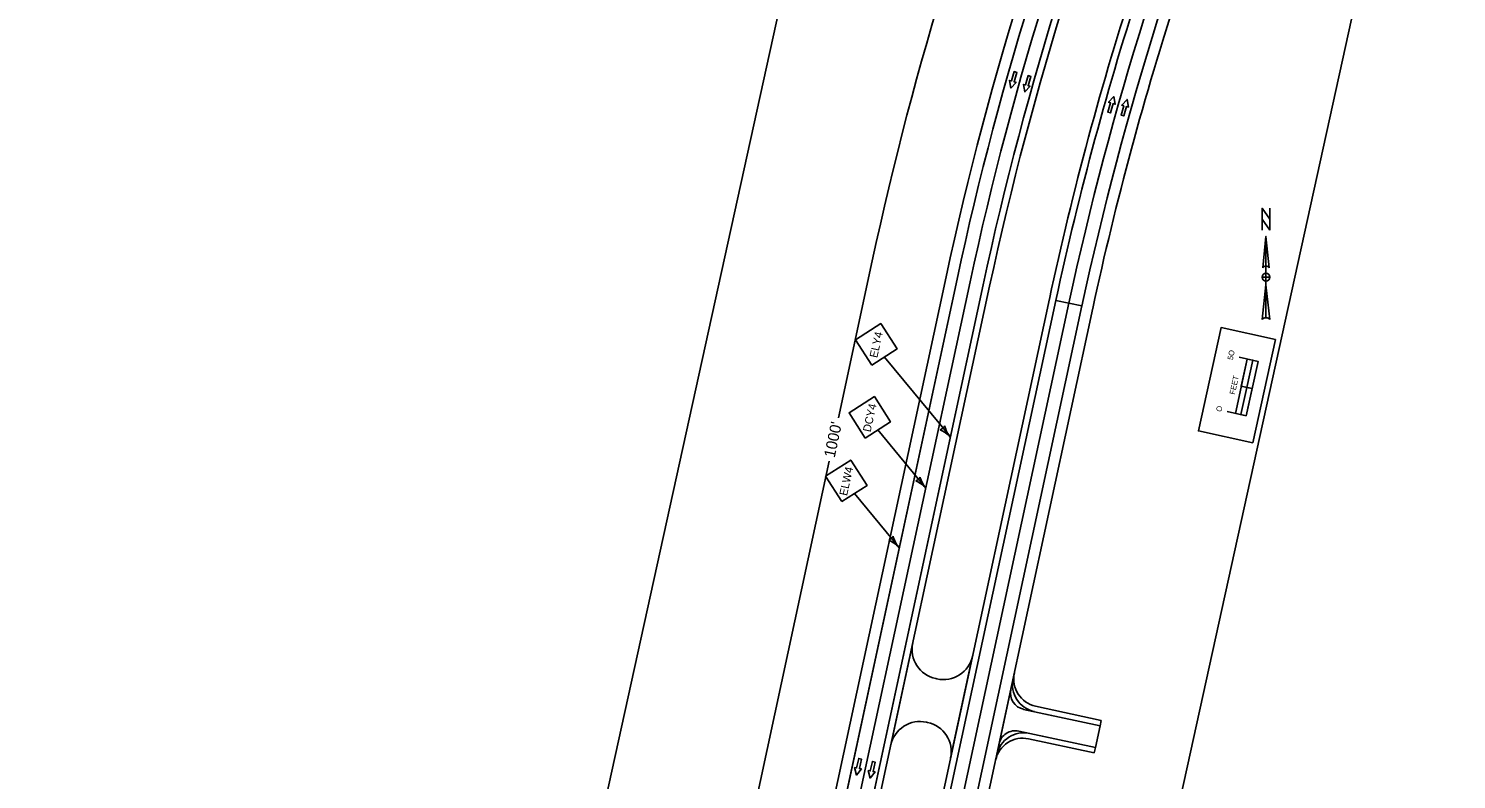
# Model space of a CAD drawing. Extents: x 14104283 to 14121738, y 8635219 to 8671666.
# Drawn here: x 14108141 to 14109426, y 8644454 to 8645129 of the extents above; entities that cross this region are included whole.
import ezdxf

# ---------------------------------------------------------------- set-up
doc = ezdxf.new("R2010")
doc.units = 0
for name, color, linetype in [('Cell', 7, 'Continuous'), ('Default', 7, 'Continuous'), ('dsnCellsNorthArrow', 7, 'Continuous'), ('dsnCellsScaleBlock', 7, 'Continuous'), ('dsnNonPlotable', 7, 'Continuous'), ('dsnPaintExistingBrokenLaneLineWhite', 7, 'Continuous'), ('dsnPaintExistingEdgeLineLeftYellow', 7, 'Continuous'), ('dsnPaintExistingEdgeLineRightWhite', 7, 'Continuous'), ('dsnShadingPaved', 7, 'Continuous'), ('dsnStdLabel', 7, 'Continuous'), ('dsnStgShadingPrevPav', 7, 'Continuous')]:
    doc.layers.add(name, color=color, linetype=linetype)

msp = doc.modelspace()

# ---------------------------------------------------------------- linework, layer by layer
at = {"layer": 'Cell'}
for points in [[(14109027.8, 8645090.4), (14109030.2, 8645089.7), (14109027.7, 8645081.3), (14109029.5, 8645080.7), (14109024.8, 8645075.6), (14109023.5, 8645082.5), (14109025.3, 8645082)], [(14109040.4, 8645086.8), (14109042.8, 8645086.1), (14109040.3, 8645077.7), (14109042.1, 8645077.2), (14109037.4, 8645072.1), (14109036.1, 8645078.9), (14109037.9, 8645078.4)], [(14109114.4, 8645053.2), (14109112, 8645054), (14109114.5, 8645062.3), (14109112.7, 8645062.9), (14109117.4, 8645068), (14109118.7, 8645061.1), (14109116.9, 8645061.6)], [(14109126.3, 8645050.6), (14109123.9, 8645051.3), (14109126.3, 8645059.7), (14109124.5, 8645060.3), (14109129.3, 8645065.4), (14109130.5, 8645058.5), (14109128.7, 8645059)], [(14108887.8, 8644472.9), (14108890.2, 8644472.3), (14108888.4, 8644463.8), (14108890.2, 8644463.4), (14108885.8, 8644457.9), (14108884.1, 8644464.7), (14108885.9, 8644464.3)], [(14108900.1, 8644470.2), (14108902.5, 8644469.6), (14108900.7, 8644461.1), (14108902.5, 8644460.7), (14108898.1, 8644455.2), (14108896.4, 8644462), (14108898.2, 8644461.6)]]:
    msp.add_lwpolyline(points, close=True, dxfattribs=at)
for points in [[(14109025.3, 8645082), (14109023.5, 8645082.5), (14109024.8, 8645075.6), (14109029.5, 8645080.7), (14109027.7, 8645081.3), (14109030.2, 8645089.7), (14109027.8, 8645090.4), (14109025.3, 8645082)], [(14109037.9, 8645078.4), (14109036.1, 8645078.9), (14109037.4, 8645072.1), (14109042.1, 8645077.2), (14109040.3, 8645077.7), (14109042.8, 8645086.1), (14109040.4, 8645086.8), (14109037.9, 8645078.4)], [(14109116.9, 8645061.6), (14109118.7, 8645061.1), (14109117.4, 8645068), (14109112.7, 8645062.9), (14109114.5, 8645062.3), (14109112, 8645054), (14109114.4, 8645053.2), (14109116.9, 8645061.6)], [(14109128.7, 8645059), (14109130.5, 8645058.5), (14109129.3, 8645065.4), (14109124.5, 8645060.3), (14109126.3, 8645059.7), (14109123.9, 8645051.3), (14109126.3, 8645050.6), (14109128.7, 8645059)], [(14108885.9, 8644464.3), (14108884.1, 8644464.7), (14108885.8, 8644457.9), (14108890.2, 8644463.4), (14108888.4, 8644463.8), (14108890.2, 8644472.3), (14108887.8, 8644472.9), (14108885.9, 8644464.3)], [(14108898.2, 8644461.6), (14108896.4, 8644462), (14108898.1, 8644455.2), (14108902.5, 8644460.7), (14108900.7, 8644461.1), (14108902.5, 8644469.6), (14108900.1, 8644470.2), (14108898.2, 8644461.6)]]:
    msp.add_lwpolyline(points, dxfattribs=at)
at = {"layer": 'Default'}
for p, q in [((14108700.5, 8643190.8), (14109065.3, 8644884.7)), ((14109088.7, 8644879.7), (14108724, 8643185.8)), ((14109065.3, 8644884.7), (14109088.7, 8644879.7))]:
    msp.add_line(p, q, dxfattribs=at)
for points in [[(14108976.3, 8644903.9), (14108611.6, 8643210.2), (14108202.1, 8641346.1)], [(14108434.9, 8642294.1), (14108635.1, 8643205.1), (14108999.8, 8644898.8)]]:
    msp.add_lwpolyline(points, dxfattribs=at)
for radius in [2968, 2944]:
    msp.add_arc((14111877.8, 8644279.1), radius, 157.1547, 167.8488, dxfattribs=at)
at = {"layer": 'dsnCellsNorthArrow'}
for p, q in [((14109254.3, 8644942.2), (14109257.1, 8644914.1)), ((14109254.3, 8644942.2), (14109254.3, 8644869)), ((14109251.5, 8644914.1), (14109251.5, 8644914.1)), ((14109251.6, 8644914.3), (14109252.1, 8644914.9)), ((14109250.8, 8644867.6), (14109254.3, 8644898.6)), ((14109254.3, 8644902.1), (14109254.3, 8644902.1))]:
    msp.add_line(p, q, dxfattribs=at)
msp.add_lwpolyline([(14109257.8, 8644947.9), (14109250.8, 8644957.7), (14109250.8, 8644967.6), (14109257.8, 8644957.7)], close=True, dxfattribs=at)
for points in [[(14109250.8, 8644947.9), (14109250.8, 8644967.6), (14109257.8, 8644957.7), (14109257.8, 8644967.6)], [(14109251.5, 8644914.1), (14109254.3, 8644942.2), (14109254.3, 8644915.5)], [(14109254.3, 8644902.1), (14109254.3, 8644905.6), (14109250.8, 8644905.6)], [(14109257.8, 8644905.6), (14109254.3, 8644905.6), (14109254.3, 8644909.1)], [(14109254.3, 8644869), (14109254.3, 8644898.6), (14109257.8, 8644867.6)]]:
    msp.add_lwpolyline(points, dxfattribs=at)
for centre, radius, start, end in [((14109254.3, 8644905.6), 3.52, 90, 180), ((14109254.3, 8644905.6), 3.52, 180, 270), ((14109254.3, 8644912), 3.52, 90.0204, 143.1257), ((14109254.3, 8644912), 3.52, 36.8481, 90.0218), ((14109254.3, 8644905.6), 3.52, 0, 90), ((14109254.3, 8644905.6), 3.52, 270, 360), ((14109254.3, 8644863.9), 5.1, 89.9894, 133.619), ((14109254.3, 8644863.9), 5.11, 46.4021, 90.0006)]:
    msp.add_arc(centre, radius, start, end, dxfattribs=at)
at = {"layer": 'dsnCellsScaleBlock'}
msp.add_line((14109241.9, 8644805.4), (14109232.1, 8644807.6), dxfattribs=at)
msp.add_line((14109241.9, 8644805.4), (14109232.1, 8644807.6), dxfattribs=at)
for points in [[(14109242.5, 8644756.7), (14109193.6, 8644767.4), (14109214, 8644860.2), (14109262.8, 8644849.4)], [(14109193.6, 8644767.4), (14109214, 8644860.2), (14109262.8, 8644849.4), (14109242.5, 8644756.7)], [(14109242.5, 8644756.7), (14109193.6, 8644767.4), (14109214, 8644860.2), (14109262.8, 8644849.4)], [(14109237, 8644806.5), (14109242.4, 8644830.9), (14109237.5, 8644832), (14109232.1, 8644807.6)], [(14109236.5, 8644781), (14109241.9, 8644805.4), (14109237, 8644806.5), (14109231.6, 8644782.1)]]:
    msp.add_lwpolyline(points, close=True, dxfattribs=at)
for points in [[(14109219.4, 8644784.8), (14109236.5, 8644781), (14109247.3, 8644829.8), (14109230.2, 8644833.6)], [(14109226.8, 8644783.1), (14109237.5, 8644832)]]:
    msp.add_lwpolyline(points, dxfattribs=at)
at = {"layer": 'dsnNonPlotable'}
msp.add_lwpolyline([(14108596.1, 8644144.9), (14108932.5, 8645675.8), (14109425.7, 8645567.5), (14109089.3, 8644036.5)], close=True, dxfattribs=at)
at = {"layer": 'dsnPaintExistingBrokenLaneLineWhite'}
msp.add_line((14108623.3, 8643207.7), (14108988, 8644901.3), dxfattribs=at)
msp.add_lwpolyline([(14108306.4, 8641340.7), (14108389, 8641717), (14108712.3, 8643188.3), (14108894.6, 8644035.3), (14109077, 8644882.2)], dxfattribs=at)
for radius in [2956, 2865]:
    msp.add_arc((14111877.8, 8644279.1), radius, 157.1547, 167.8488, dxfattribs=at)
at = {"layer": 'dsnPaintExistingEdgeLineLeftYellow'}
msp.add_line((14108700.5, 8643190.8), (14109065.3, 8644884.7), dxfattribs=at)
msp.add_lwpolyline([(14108999.8, 8644898.8), (14108635.1, 8643205.1), (14108434.9, 8642294.1)], dxfattribs=at)
for radius, start in [(2944, 157.1547), (2877, 161.903)]:
    msp.add_arc((14111877.8, 8644279.1), radius, start, 167.8488, dxfattribs=at)
at = {"layer": 'dsnPaintExistingEdgeLineRightWhite'}
msp.add_line((14108724, 8643185.8), (14109088.7, 8644879.7), dxfattribs=at)
msp.add_lwpolyline([(14108976.3, 8644903.9), (14108611.6, 8643210.2), (14108202.1, 8641346.1)], dxfattribs=at)
for radius in [2968, 2853]:
    msp.add_arc((14111877.8, 8644279.1), radius, 157.1547, 167.8488, dxfattribs=at)
at = {"layer": 'dsnShadingPaved'}
msp.add_line((14109088.7, 8644879.7), (14109065.3, 8644884.7), dxfattribs=at)
for radius, start in [(2853, 157.1547), (2877, 161.903)]:
    msp.add_arc((14111877.8, 8644279.1), radius, start, 167.8488, dxfattribs=at)
at = {"layer": 'dsnStdLabel'}
for p, q in [((14108900, 8644920.3), (14108869.6, 8644779.2)), ((14108910.9, 8644833.8), (14108970.3, 8644761.9)), ((14108905, 8644768.2), (14108948.2, 8644715.9)), ((14108861.2, 8644740.1), (14108659.4, 8643802.5)), ((14108883.9, 8644711.1), (14108923.9, 8644662.7))]:
    msp.add_line(p, q, dxfattribs=at)
for points in [[(14108899.5, 8644826.5), (14108922.3, 8644841.1), (14108907.7, 8644863.8), (14108885, 8644849.3)], [(14108893.7, 8644760.9), (14108916.4, 8644775.5), (14108901.9, 8644798.2), (14108879.1, 8644783.7)], [(14108872.5, 8644703.8), (14108895.3, 8644718.4), (14108880.7, 8644741.1), (14108858, 8644726.6)]]:
    msp.add_lwpolyline(points, close=True, dxfattribs=at)
for centre, radius, start, end in [((14111877.8, 8644279.1), 3046, 157.7272, 167.8488), ((14108957.8, 8644776.5), 8.86, 292.8385, 328.307), ((14108952.8, 8644746.9), 22.9, 40.5727, 68.6439), ((14108987.7, 8644776.8), 22.9, 192.5015, 220.5728), ((14108935.7, 8644730.5), 8.86, 292.8385, 328.307), ((14108965.6, 8644730.8), 22.9, 192.5015, 220.5728), ((14108930.8, 8644701), 22.9, 40.5727, 68.6439), ((14108911.4, 8644677.3), 8.86, 292.8385, 328.307), ((14108941.3, 8644677.6), 22.9, 192.5015, 220.5728), ((14108906.5, 8644647.7), 22.9, 40.5727, 68.6439)]:
    msp.add_arc(centre, radius, start, end, dxfattribs=at)
at = {"layer": 'dsnStgShadingPrevPav'}
for p, q in [((14108601.8, 8643212.3), (14108966.5, 8644906)), ((14108976.3, 8644903.9), (14108611.6, 8643210.2)), ((14109059.4, 8644886), (14108694.7, 8643192.1)), ((14108733.8, 8643183.6), (14109098.5, 8644877.6)), ((14108936.5, 8644576.7), (14108916.8, 8644484.8)), ((14108970.5, 8644473.3), (14108990.3, 8644565.1)), ((14108958.2, 8644544.4), (14108957.2, 8644544.6)), ((14109026.8, 8644544.6), (14109024.7, 8644534.9)), ((14109027.9, 8644549.5), (14109026.8, 8644544.6)), ((14109024.7, 8644534.9), (14109014.2, 8644486)), ((14109106.1, 8644507.1), (14109047, 8644519.8)), ((14108948.8, 8644505.5), (14108949.8, 8644505.3)), ((14109105.1, 8644502.2), (14109036.2, 8644517)), ((14109036.2, 8644517), (14109046, 8644514.9)), ((14109046, 8644514.9), (14109105.1, 8644502.2)), ((14109105.1, 8644502.2), (14109106.1, 8644507.1)), ((14109032, 8644497.5), (14109100.8, 8644482.7)), ((14109041.8, 8644495.4), (14109032, 8644497.5)), ((14109100.8, 8644482.7), (14109041.8, 8644495.4)), ((14109100.8, 8644482.7), (14109105.1, 8644502.2)), ((14109014.2, 8644486), (14109012.1, 8644476.2)), ((14109040.7, 8644490.5), (14109099.8, 8644477.8)), ((14109099.8, 8644477.8), (14109100.8, 8644482.7)), ((14109012.1, 8644476.2), (14109011, 8644471.3))]:
    msp.add_line(p, q, dxfattribs=at)
for points in [[(14108202.1, 8641346.1), (14108611.6, 8643210.2), (14108976.3, 8644903.9)], [(14108999.8, 8644898.8), (14108817.4, 8644052), (14108635.1, 8643205.1), (14108387.9, 8642080.1), (14108140.8, 8640955.1)], [(14108146.7, 8640953.8), (14108640.9, 8643203.9), (14109005.6, 8644897.6)], [(14108999.8, 8644898.8), (14108635.1, 8643205.1), (14108225.5, 8641340.9)]]:
    msp.add_lwpolyline(points, dxfattribs=at)
for centre, radius, start, end in [((14111877.8, 8644279.1), 2978, 157.1547, 167.8488), ((14111877.8, 8644279.1), 2968, 157.1547, 167.8488), ((14111877.8, 8644279.1), 2968, 157.1547, 167.8488), ((14111877.8, 8644279.1), 2944, 157.1547, 167.8488), ((14111877.8, 8644279.1), 2944, 157.1547, 167.8488), ((14111877.8, 8644279.1), 2938, 157.1547, 167.8488), ((14111877.8, 8644279.1), 2883, 161.9025, 167.8488), ((14111877.8, 8644279.1), 2843, 161.9025, 167.8488), ((14108962.9, 8644571), 27, 167.8488, 257.8488), ((14108963.9, 8644570.8), 27, 257.8488, 347.8488), ((14109051.2, 8644539.4), 25, 167.8488, 257.8481), ((14109051.2, 8644539.4), 25, 167.8488, 257.8481), ((14109052.3, 8644544.3), 25, 167.8488, 257.8488), ((14109039.4, 8644531.7), 15, 167.8488, 257.8488), ((14109039.4, 8644531.7), 15, 167.8488, 257.8488), ((14108943.1, 8644479.1), 27, 77.8488, 167.8488), ((14108944.1, 8644478.9), 27, 347.8488, 77.8488), ((14109036.5, 8644470.9), 25, 77.8488, 167.848), ((14109036.5, 8644470.9), 25, 77.8488, 167.848), ((14109028.8, 8644482.8), 15, 77.8488, 167.8488), ((14109028.8, 8644482.8), 15, 77.8488, 167.8488), ((14109035.5, 8644466.1), 25, 77.8488, 167.8488)]:
    msp.add_arc(centre, radius, start, end, dxfattribs=at)

# ---------------------------------------------------------------- texts
at = {"layer": 'dsnCellsScaleBlock'}
for s, p in [('5O', (14109224.4, 8644830.7)), ('FEET', (14109226.3, 8644799.7)), ('O', (14109214.2, 8644784.2))]:
    msp.add_text(s, height=5, rotation=77.6078, dxfattribs=at).set_placement(p)
at = {"layer": 'dsnStdLabel'}
for s, height, rotation, p in [('ELY4', 7.2, 77.6078, (14108904.5, 8644832.6)), ('DCY4', 7.2, 77.6078, (14108898.5, 8644765.9)), ("1000'", 10, 78.0531, (14108866.2, 8644742.7)), ('ELW4', 7.2, 77.6078, (14108877.3, 8644708.6))]:
    msp.add_text(s, height=height, rotation=rotation, dxfattribs=at).set_placement(p)

doc.saveas('drawing.dxf')
